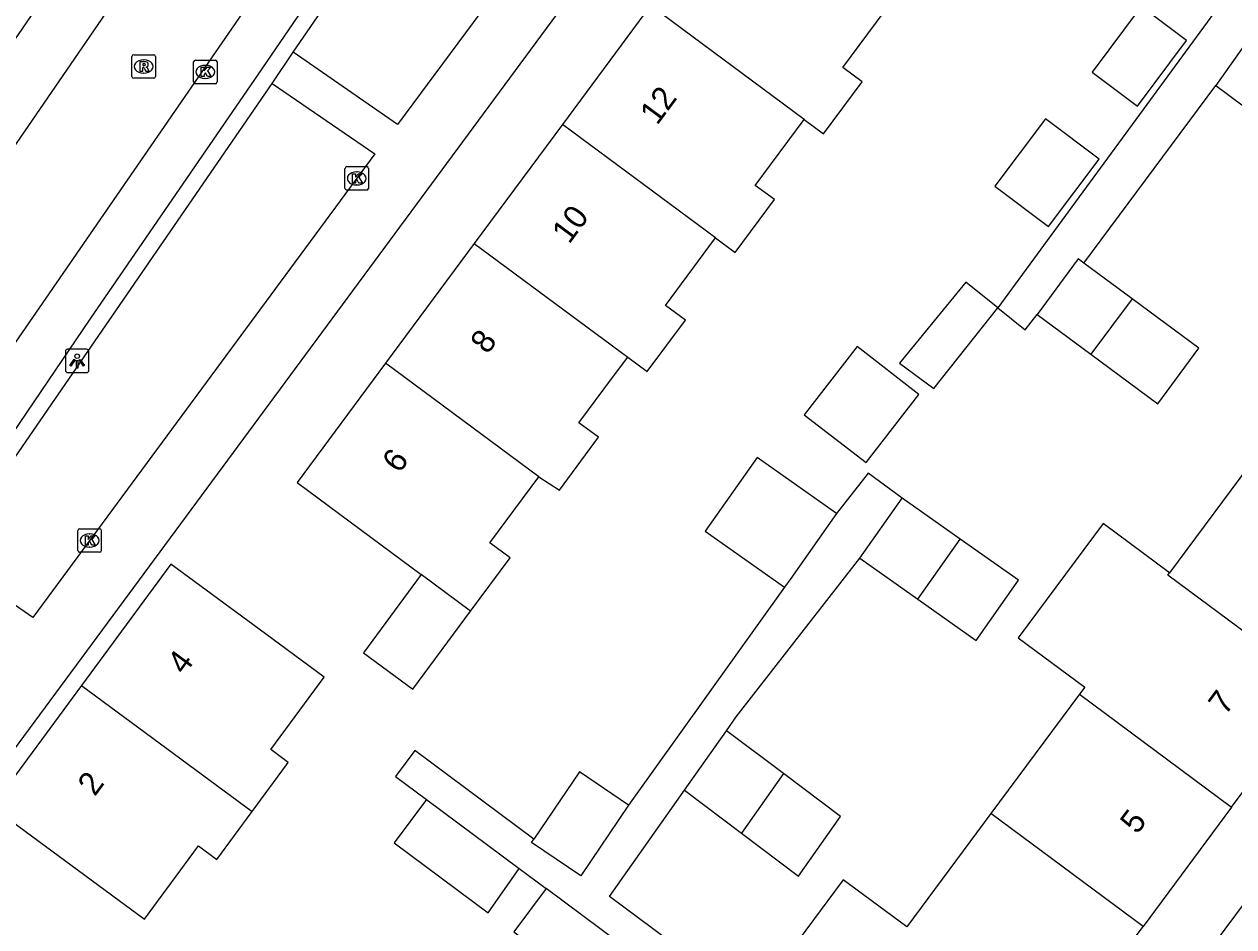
# Model space of a CAD drawing. Extents: x 160026 to 161302, y 384757 to 385701.
# Drawn here: x 160248.6 to 160300.1, y 385206.4 to 385244.8 of the extents above; entities that cross this region are included whole.
import ezdxf

# ---------------------------------------------------------------- set-up
doc = ezdxf.new("R2010")
doc.units = 0
for name, color, linetype in [('IMGEO_Kolk', 7, 'Continuous'), ('IMGEO_Lichtpunt', 7, 'Continuous'), ('IMGEO_Pand', 7, 'Continuous'), ('IMGEO_Pand_nummerreeks', 7, 'Continuous'), ('IMGEO_Rijbaan_lokaal_open', 7, 'Continuous'), ('IMGEO_Rioolput', 7, 'Continuous'), ('IMGEO_Voetpad_open', 7, 'Continuous')]:
    doc.layers.add(name, color=color, linetype=linetype)

msp = doc.modelspace()

# ---------------------------------------------------------------- linework, layer by layer
at = {"layer": 'IMGEO_Kolk'}
for p, q in [((160255.785, 385242.298), (160255.785, 385243.15)), ((160255.86, 385243.224), (160256.712, 385243.224)), ((160256.273, 385243.004), (160256.298, 385243.004)), ((160256.786, 385243.15), (160256.786, 385242.298)), ((160256.296, 385242.444), (160256.271, 385242.444)), ((160256.712, 385242.224), (160255.86, 385242.224)), ((160262.231, 385237.768), (160262.231, 385238.62)), ((160262.306, 385238.694), (160263.158, 385238.694)), ((160262.719, 385238.474), (160262.744, 385238.474)), ((160263.232, 385238.62), (160263.232, 385237.768)), ((160262.742, 385237.914), (160262.717, 385237.914)), ((160263.158, 385237.694), (160262.306, 385237.694)), ((160250.932, 385223.284), (160251.784, 385223.284)), ((160250.857, 385222.358), (160250.857, 385223.21)), ((160251.345, 385223.064), (160251.37, 385223.064)), ((160251.858, 385223.21), (160251.858, 385222.358)), ((160251.784, 385222.284), (160250.932, 385222.284)), ((160251.368, 385222.504), (160251.343, 385222.504))]:
    msp.add_line(p, q, dxfattribs=at)
for points in [[(160255.785, 385242.298), (160255.785, 385243.15)], [(160255.86, 385243.224), (160256.712, 385243.224)], [(160256.106, 385242.924), (160256.229, 385242.924), (160256.229, 385242.773), (160256.359, 385242.924), (160256.523, 385242.924), (160256.377, 385242.773), (160256.53, 385242.524), (160256.378, 385242.524), (160256.293, 385242.688), (160256.229, 385242.621), (160256.229, 385242.524), (160256.106, 385242.524), (160256.106, 385242.924)], [(160256.786, 385243.15), (160256.786, 385242.298)], [(160256.712, 385242.224), (160255.86, 385242.224)], [(160262.231, 385237.768), (160262.231, 385238.62)], [(160262.306, 385238.694), (160263.158, 385238.694)], [(160262.552, 385238.394), (160262.675, 385238.394), (160262.675, 385238.243), (160262.805, 385238.394), (160262.969, 385238.394), (160262.823, 385238.243), (160262.976, 385237.994), (160262.824, 385237.994), (160262.739, 385238.158), (160262.675, 385238.091), (160262.675, 385237.994), (160262.552, 385237.994), (160262.552, 385238.394)], [(160263.232, 385238.62), (160263.232, 385237.768)], [(160263.158, 385237.694), (160262.306, 385237.694)], [(160250.932, 385223.284), (160251.784, 385223.284)], [(160250.857, 385222.358), (160250.857, 385223.21)], [(160251.178, 385222.984), (160251.301, 385222.984), (160251.301, 385222.833), (160251.431, 385222.984), (160251.595, 385222.984), (160251.449, 385222.833), (160251.602, 385222.584), (160251.45, 385222.584), (160251.365, 385222.748), (160251.301, 385222.681), (160251.301, 385222.584), (160251.178, 385222.584), (160251.178, 385222.984)], [(160251.858, 385223.21), (160251.858, 385222.358)], [(160251.784, 385222.284), (160250.932, 385222.284)]]:
    msp.add_lwpolyline(points, dxfattribs=at)
for centre, start, end in [((160255.862, 385243.148), 91.552, 178.448), ((160255.862, 385243.148), 91.552, 178.448), ((160256.71, 385243.148), 1.552, 88.448), ((160256.71, 385243.148), 1.552, 88.448), ((160255.862, 385242.3), 181.552, 268.448), ((160255.862, 385242.3), 181.552, 268.448), ((160256.71, 385242.3), 271.552, 358.448), ((160256.71, 385242.3), 271.552, 358.448), ((160262.308, 385238.618), 91.552, 178.448), ((160262.308, 385238.618), 91.552, 178.448), ((160263.156, 385238.618), 1.552, 88.448), ((160263.156, 385238.618), 1.552, 88.448), ((160262.308, 385237.77), 181.552, 268.448), ((160262.308, 385237.77), 181.552, 268.448), ((160263.156, 385237.77), 271.552, 358.448), ((160263.156, 385237.77), 271.552, 358.448), ((160250.934, 385223.208), 91.552, 178.448), ((160250.934, 385223.208), 91.552, 178.448), ((160251.782, 385223.208), 1.552, 88.448), ((160251.782, 385223.208), 1.552, 88.448), ((160250.934, 385222.36), 181.552, 268.448), ((160250.934, 385222.36), 181.552, 268.448), ((160251.782, 385222.36), 271.552, 358.448), ((160251.782, 385222.36), 271.552, 358.448)]:
    msp.add_arc(centre, 0.0765, start, end, dxfattribs=at)
for centre, major_axis, ratio, start_param, end_param in [((160256.272, 385242.724), (-0.387, 0.002), 0.722429, 4.712389, 7.853982), ((160256.297, 385242.724), (-0.39, 0.002), 0.717154, 1.570796, 4.712389), ((160262.718, 385238.194), (-0.387, 0.002), 0.722429, 4.712389, 7.853982), ((160262.743, 385238.194), (-0.39, 0.002), 0.717154, 1.570796, 4.712389), ((160251.344, 385222.784), (-0.387, 0.002), 0.722429, 4.712389, 7.853982), ((160251.369, 385222.784), (-0.39, 0.002), 0.717154, 1.570796, 4.712389)]:
    msp.add_ellipse(centre, major_axis=major_axis, ratio=ratio, start_param=start_param, end_param=end_param, dxfattribs=at)
at = {"layer": 'IMGEO_Lichtpunt'}
for p, q in [((160250.33, 385230.832), (160250.33, 385230.025)), ((160250.33, 385230.832), (160250.33, 385230.025)), ((160251.232, 385230.927), (160250.424, 385230.927)), ((160251.232, 385230.927), (160250.424, 385230.927)), ((160251.326, 385230.025), (160251.326, 385230.832)), ((160251.326, 385230.025), (160251.326, 385230.832)), ((160250.424, 385229.931), (160251.232, 385229.931)), ((160250.424, 385229.931), (160251.232, 385229.931))]:
    msp.add_line(p, q, dxfattribs=at)
for points in [[(160250.704, 385230.496), (160250.743, 385230.468), (160250.555, 385230.206), (160250.517, 385230.233), (160250.704, 385230.496)], [(160250.916, 385230.468), (160250.954, 385230.495), (160251.141, 385230.233), (160251.102, 385230.205), (160250.916, 385230.468)], [(160250.806, 385230.448), (160250.853, 385230.448), (160250.853, 385230.126), (160250.806, 385230.126), (160250.806, 385230.448)]]:
    msp.add_lwpolyline(points, dxfattribs=at)
msp.add_circle((160250.829, 385230.63), 0.0994, dxfattribs=at)
for centre, start, end in [((160250.424, 385230.832), 90, 180), ((160250.424, 385230.832), 90, 180), ((160251.232, 385230.832), 0, 90), ((160251.232, 385230.832), 0, 90), ((160250.424, 385230.025), 180, 270), ((160250.424, 385230.025), 180, 270), ((160251.232, 385230.025), 270, 0), ((160251.232, 385230.025), 270, 360)]:
    msp.add_arc(centre, 0.0946, start, end, dxfattribs=at)
at = {"layer": 'IMGEO_Pand'}
for points in [[(160275.233, 385245.549), (160271.488, 385240.493)], [(160281.774, 385240.7), (160275.233, 385245.549)], [(160281.774, 385240.7), (160282.601, 385240.087), (160284.246, 385242.308), (160283.428, 385242.914), (160285.548, 385245.775), (160285.582, 385245.821)], [(160296.132, 385245.505), (160294.039, 385242.72), (160295.963, 385241.274), (160298.056, 385244.058), (160296.132, 385245.505)], [(160301.114, 385244.72), (160299.305, 385242.153)], [(160299.305, 385242.153), (160301.738, 385240.336)], [(160271.488, 385240.493), (160267.737, 385235.429)], [(160278.008, 385235.663), (160271.488, 385240.493)], [(160278.008, 385235.663), (160278.848, 385235.04), (160280.516, 385237.291), (160279.698, 385237.897), (160281.774, 385240.7)], [(160292.05, 385240.731), (160289.893, 385237.863), (160292.179, 385236.145), (160294.335, 385239.013), (160292.05, 385240.731)], [(160274.265, 385230.591), (160275.101, 385229.972), (160276.722, 385232.161), (160275.877, 385232.787), (160277.968, 385235.609), (160278.008, 385235.663)], [(160267.737, 385235.429), (160263.96, 385230.331)], [(160267.737, 385235.429), (160274.265, 385230.591)], [(160293.68, 385234.594), (160293.445, 385234.768), (160291.699, 385232.408)], [(160295.735, 385233.073), (160293.68, 385234.594)], [(160290.027, 385232.684), (160288.666, 385233.783), (160285.843, 385230.333), (160287.304, 385229.252), (160290.027, 385232.684)], [(160295.735, 385233.073), (160293.988, 385230.713)], [(160293.988, 385230.713), (160296.838, 385228.604), (160298.585, 385230.964), (160295.735, 385233.073)], [(160291.699, 385232.408), (160293.988, 385230.713)], [(160286.658, 385229), (160284.031, 385231.038), (160281.782, 385228.14), (160284.412, 385226.102), (160286.658, 385229)], [(160270.483, 385225.498), (160271.357, 385224.931), (160273.021, 385227.177), (160272.192, 385227.792), (160273.626, 385229.728), (160274.265, 385230.591)], [(160263.96, 385230.331), (160260.197, 385225.251), (160264.215, 385222.275), (160265.479, 385221.338)], [(160270.483, 385225.498), (160263.96, 385230.331)], [(160301.06, 385226.428), (160297.333, 385221.408)], [(160283.153, 385223.929), (160279.783, 385226.316), (160277.567, 385223.185), (160280.936, 385220.799)], [(160267.578, 385219.783), (160269.262, 385222.056), (160268.404, 385222.691), (160270.483, 385225.498)], [(160284.142, 385222.031), (160285.944, 385224.589)], [(160288.425, 385222.841), (160285.944, 385224.589)], [(160283.153, 385223.929), (160281.204, 385221.177), (160280.936, 385220.799)], [(160297.333, 385221.408), (160294.508, 385223.506), (160290.895, 385218.639), (160293.72, 385216.542), (160293.5, 385216.245)], [(160286.624, 385220.284), (160288.425, 385222.841)], [(160286.624, 385220.284), (160289.105, 385218.536), (160290.906, 385221.093), (160288.425, 385222.841)], [(160258.277, 385211.254), (160259.743, 385213.24), (160259.818, 385213.342), (160259.077, 385213.889), (160261.347, 385216.965), (160258.846, 385218.812), (160254.823, 385221.781), (160251.012, 385216.618)], [(160284.142, 385222.031), (160286.624, 385220.284)], [(160265.479, 385221.338), (160263.015, 385218.012), (160265.114, 385216.457), (160267.578, 385219.783)], [(160267.578, 385219.783), (160265.479, 385221.338)], [(160303.741, 385216.506), (160297.264, 385221.315), (160297.333, 385221.408)], [(160251.012, 385216.618), (160247.202, 385211.456), (160253.689, 385206.668), (160255.994, 385209.792), (160256.773, 385209.217), (160258.277, 385211.254)], [(160251.012, 385216.618), (160258.277, 385211.254)], [(160293.5, 385216.245), (160289.729, 385211.165)], [(160293.5, 385216.245), (160299.977, 385211.436)], [(160299.977, 385211.436), (160303.741, 385216.506)], [(160276.681, 385212.159), (160278.468, 385214.694)], [(160280.896, 385212.87), (160278.468, 385214.694)], [(160274.306, 385211.532), (160272.214, 385212.948), (160270.275, 385210.084)], [(160280.896, 385212.87), (160279.109, 385210.335)], [(160279.109, 385210.335), (160281.537, 385208.511), (160283.324, 385211.047), (160280.896, 385212.87)], [(160276.681, 385212.159), (160279.109, 385210.335)], [(160265.701, 385211.768), (160264.327, 385209.919), (160268.333, 385206.942), (160269.652, 385208.832)], [(160265.701, 385211.768), (160269.652, 385208.832)], [(160274.306, 385211.532), (160272.271, 385208.523), (160270.177, 385209.939), (160270.275, 385210.084)], [(160289.729, 385211.165), (160286.151, 385206.345)], [(160296.205, 385206.356), (160289.729, 385211.165)], [(160299.977, 385211.436), (160296.205, 385206.356)], [(160286.151, 385206.345), (160283.445, 385208.354), (160279.609, 385203.188), (160282.315, 385201.179), (160282.268, 385201.116)], [(160270.799, 385207.98), (160269.424, 385206.131), (160273.382, 385203.189), (160274.701, 385205.079)], [(160274.701, 385205.079), (160270.799, 385207.98)], [(160292.392, 385201.22), (160296.205, 385206.356)]]:
    msp.add_lwpolyline(points, dxfattribs=at)
at = {"layer": 'IMGEO_Rijbaan_lokaal_open'}
for points in [[(160289.671, 385300.047), (160275.192, 385279.056), (160273.555, 385276.635), (160266.052, 385265.629), (160255.317, 385250), (160244.457, 385234.203)], [(160237.121, 385215.152), (160274.133, 385268.809), (160281.342, 385279.321), (160281.354, 385279.339)]]:
    msp.add_lwpolyline(points, dxfattribs=at)
at = {"layer": 'IMGEO_Rioolput'}
for p, q in [((160253.161, 385242.528), (160253.161, 385243.38)), ((160253.236, 385243.454), (160254.088, 385243.454)), ((160254.162, 385243.38), (160254.162, 385242.528)), ((160253.649, 385243.234), (160253.674, 385243.234)), ((160254.088, 385242.454), (160253.236, 385242.454)), ((160253.672, 385242.674), (160253.647, 385242.674))]:
    msp.add_line(p, q, dxfattribs=at)
for points in [[(160253.161, 385242.528), (160253.161, 385243.38)], [(160253.236, 385243.454), (160254.088, 385243.454)], [(160254.162, 385243.38), (160254.162, 385242.528)], [(160253.75, 385243.152), (160253.498, 385243.154), (160253.498, 385242.754)], [(160253.498, 385242.754), (160253.622, 385242.754), (160253.622, 385242.916), (160253.633, 385242.916)], [(160253.676, 385243.073), (160253.622, 385243.073), (160253.622, 385242.992)], [(160253.622, 385242.992), (160253.674, 385242.992)], [(160253.68, 385242.887), (160253.751, 385242.754), (160253.891, 385242.754), (160253.826, 385242.88)], [(160254.088, 385242.454), (160253.236, 385242.454)]]:
    msp.add_lwpolyline(points, dxfattribs=at)
for centre, radius, start, end in [((160253.238, 385243.378), 0.0765, 91.552, 178.448), ((160253.238, 385243.378), 0.0765, 91.552, 178.448), ((160254.086, 385243.378), 0.0765, 1.552, 88.448), ((160254.086, 385243.378), 0.0765, 1.552, 88.448), ((160253.632, 385242.863), 0.0533, 26.0293, 88.6989), ((160253.658, 385243.181), 0.19, 274.7715, 282.9687), ((160253.682, 385242.977), 0.0964, 77.0061, 93.1865), ((160253.696, 385243.034), 0.0378, 276.6634, 79.6772), ((160253.749, 385243.042), 0.109, 350.3612, 89.416), ((160253.747, 385243.042), 0.112, 277.5842, 350.9817), ((160253.731, 385242.827), 0.108, 29.5134, 73.7905), ((160253.238, 385242.53), 0.0765, 181.552, 268.448), ((160253.238, 385242.53), 0.0765, 181.552, 268.448), ((160254.086, 385242.53), 0.0765, 271.552, 358.448), ((160254.086, 385242.53), 0.0765, 271.552, 358.448)]:
    msp.add_arc(centre, radius, start, end, dxfattribs=at)
for centre, major_axis, ratio, start_param, end_param in [((160253.648, 385242.954), (-0.387, 0.002), 0.722429, 4.712389, 7.853982), ((160253.673, 385242.954), (-0.39, 0.002), 0.717154, 1.570796, 4.712389)]:
    msp.add_ellipse(centre, major_axis=major_axis, ratio=ratio, start_param=start_param, end_param=end_param, dxfattribs=at)
at = {"layer": 'IMGEO_Voetpad_open'}
for points in [[(160227.053, 385213.278), (160252.215, 385250), (160275.542, 385284.043), (160273.047, 385285.762)], [(160240.882, 385216.735), (160251.376, 385232.207), (160258.548, 385242.626), (160261.715, 385247.262), (160270.57, 385260.175), (160273.341, 385264.193), (160277.715, 385270.535), (160280.777, 385274.991), (160281.411, 385275.98)], [(160238.783, 385201.222), (160274.818, 385250), (160290.83, 385271.674)], [(160260.026, 385243.56), (160264.456, 385250), (160273.04, 385262.479)], [(160273.04, 385262.479), (160278.16, 385258.972), (160271.515, 385250), (160264.465, 385240.48), (160260.026, 385243.56)], [(160299.668, 385245.865), (160290.027, 385232.684)], [(160259.132, 385242.227), (160260.026, 385243.56)], [(160245.244, 385222.066), (160259.132, 385242.227)], [(160259.132, 385242.227), (160263.501, 385239.237), (160248.942, 385219.512), (160245.244, 385222.066)], [(160293.68, 385234.594), (160299.305, 385242.153)], [(160291.037, 385194.602), (160321.167, 385235.078)], [(160290.027, 385232.684), (160291.186, 385231.748), (160291.699, 385232.408)], [(160285.944, 385224.589), (160284.498, 385225.658), (160283.153, 385223.929)], [(160278.468, 385214.694), (160278.886, 385215.286), (160284.142, 385222.031)], [(160280.936, 385220.799), (160274.306, 385211.532)], [(160270.275, 385210.084), (160265.205, 385213.852), (160264.383, 385212.747), (160265.701, 385211.768)], [(160282.268, 385201.116), (160273.491, 385207.633), (160276.681, 385212.159)], [(160269.652, 385208.832), (160270.799, 385207.98)]]:
    msp.add_lwpolyline(points, dxfattribs=at)

# ---------------------------------------------------------------- texts
at = {"layer": 'IMGEO_Pand_nummerreeks'}
for s, rotation, p in [('12', 53.4684, (160275.519, 385240.423)), ('10', 53.4684, (160271.773, 385235.366)), ('8', 53.4684, (160268.297, 385230.674)), ('6', 53.4684, (160264.543, 385225.609)), ('4', 53.5685, (160255.393, 385217.031)), ('7', 53.4111, (160299.716, 385215.313)), ('2', 53.5685, (160251.581, 385211.866)), ('5', 53.409, (160295.957, 385210.249))]:
    msp.add_text(s, height=1, rotation=rotation, dxfattribs=at).set_placement(p)

doc.saveas('drawing.dxf')
